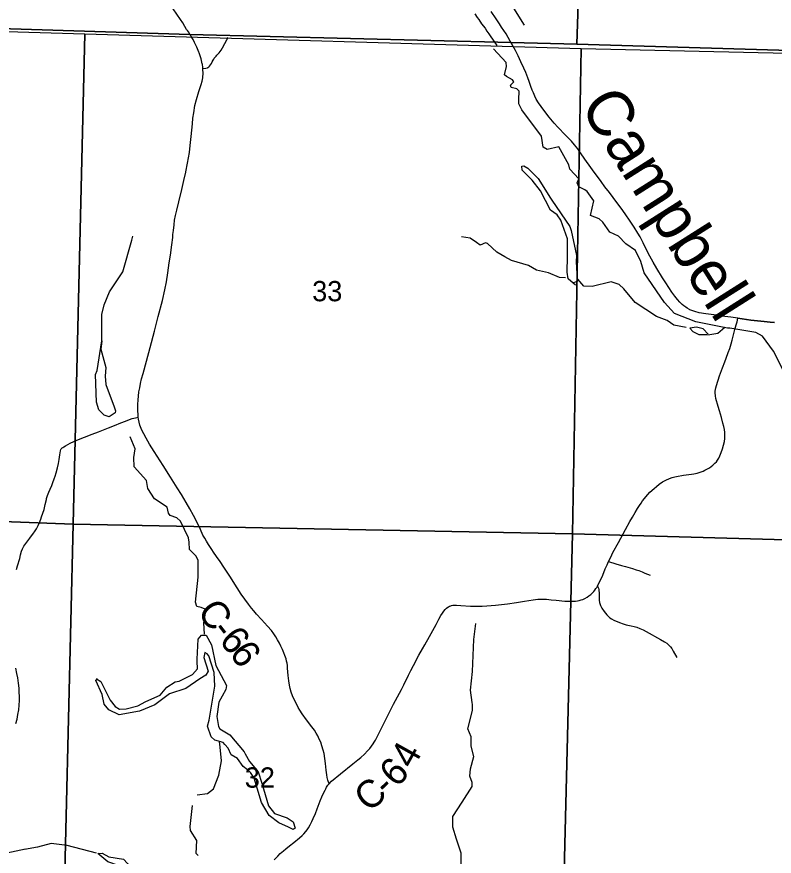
# Model space of a CAD drawing. Extents: x 0 to 34, y 0 to 22.
# Drawn here: x 5.063 to 6.627, y 14.902 to 16.635 of the extents above; entities that cross this region are included whole.
import ezdxf

# ---------------------------------------------------------------- set-up
doc = ezdxf.new("R2010")
doc.units = 0
for name, color, linetype in [('GM_X_Corporation', 7, 'Continuous'), ('GM_X_County', 7, 'Continuous'), ('GM_X_County_Road', 7, 'Continuous'), ('GM_X_County_Road_Text', 7, 'Continuous'), ('GM_X_Minor_River', 7, 'Continuous'), ('GM_X_Minor_River_Text', 7, 'Continuous'), ('GM_X_Rail_Line', 7, 'Continuous'), ('GM_X_Section_Text', 7, 'Continuous'), ('GM_X_State_Route', 7, 'Continuous'), ('GM_X_Township_Road', 7, 'Continuous')]:
    doc.layers.add(name, color=color, linetype=linetype)

msp = doc.modelspace()

# ---------------------------------------------------------------- linework, layer by layer
at = {"layer": 'GM_X_Corporation'}
for points in [[(9.4, 16.4853), (9.4, 20.4), (2.6, 20.4), (2.6, 16.6918), (3.1555, 16.6686), (3.1684, 16.6682), (4.0515, 16.6368), (4.1011, 16.6362), (4.1867, 16.6352), (4.5473, 16.6256), (4.6351, 16.6229), (5.4202, 16.5982), (6.0834, 16.5816), (6.2194, 16.578), (8.0963, 16.5226), (9.09, 16.4927)], [(6.2895, 20.4), (2.6, 20.4), (2.6, 16.6918), (3.1555, 16.6686), (3.1684, 16.6682), (4.0515, 16.6368), (4.1011, 16.6362), (4.1867, 16.6352), (4.5473, 16.6256), (4.6351, 16.6229), (5.4202, 16.5982), (6.0834, 16.5816), (6.2194, 16.578), (6.2729, 18.2077), (6.2744, 18.4654), (6.2786, 18.5898), (6.292, 18.5898), (6.2926, 19.1539), (6.2942, 19.6131), (6.2595, 19.6124)], [(9.4, 16.4853), (9.4, 20.4), (6.2895, 20.4), (6.2595, 19.6124), (6.2942, 19.6131), (6.2926, 19.1539), (6.292, 18.5898), (6.2786, 18.5898), (6.2744, 18.4654), (6.2729, 18.2077), (6.2194, 16.578), (8.0963, 16.5226), (9.09, 16.4927)], [(2.6, 16.6918), (2.6, 13.6), (9.4, 13.6), (9.4, 16.4853), (9.09, 16.4927), (8.0963, 16.5226), (6.2194, 16.578), (6.0834, 16.5816), (5.4202, 16.5982), (4.6351, 16.6229), (4.5473, 16.6256), (4.1867, 16.6352), (4.1011, 16.6362), (4.0515, 16.6368), (3.1684, 16.6682), (3.1555, 16.6686)], [(5.2032, 16.5997), (5.1793, 15.5873), (4.1616, 15.6255), (4.1862, 16.6297)], [(6.2277, 16.5693), (6.2098, 15.5669), (5.1793, 15.5873), (5.2032, 16.5997)], [(7.2336, 16.5466), (7.2151, 15.5388), (6.2098, 15.5669), (6.2277, 16.5693)], [(5.1793, 15.5873), (5.155, 14.5827), (4.1372, 14.6117), (4.1616, 15.6255)], [(5.1793, 15.5873), (6.2098, 15.5669), (6.1855, 14.5629), (5.155, 14.5827)], [(6.2098, 15.5669), (7.2151, 15.5388), (7.1913, 14.5276), (6.1855, 14.5629)]]:
    msp.add_lwpolyline(points, close=True, dxfattribs=at)
msp.add_lwpolyline([(4.5781, 13.6), (9.4, 13.6), (9.4, 16.4853), (9.09, 16.4927), (8.0963, 16.5226), (6.2194, 16.578), (6.0834, 16.5816), (5.4202, 16.5982), (4.6351, 16.6229)], dxfattribs=at)
at = {"layer": 'GM_X_County'}
msp.add_lwpolyline([(9.4, 16.4853), (9.09, 16.4927), (8.0963, 16.5226), (6.2194, 16.578), (6.0834, 16.5816), (5.4202, 16.5982), (4.6351, 16.6229), (4.5473, 16.6256), (4.1867, 16.6352), (4.1011, 16.6362), (4.0515, 16.6368), (3.1684, 16.6682), (3.1555, 16.6686), (2.6, 16.6918)], dxfattribs=at)
at = {"layer": 'GM_X_County_Road'}
for points in [[(5.5941, 14.8939), (5.6013, 14.9018), (5.6067, 14.9072), (5.6132, 14.9131), (5.6178, 14.9171), (5.6255, 14.9231), (5.6345, 14.9303), (5.6464, 14.9393), (5.6518, 14.9442), (5.6556, 14.9482), (5.6593, 14.9526), (5.6621, 14.9563), (5.6648, 14.9601), (5.6685, 14.9663), (5.6721, 14.9732), (5.6749, 14.9798), (5.6792, 14.9899), (5.6828, 14.9994), (5.6893, 15.0157), (5.6928, 15.0241), (5.6962, 15.0317), (5.6991, 15.0378), (5.7008, 15.041), (5.7024, 15.0442), (5.7052, 15.0484), (5.7074, 15.0512), (5.7047, 15.0588), (5.7034, 15.064), (5.7025, 15.0698), (5.7015, 15.0795), (5.7002, 15.0928), (5.699, 15.1032), (5.6973, 15.1135), (5.6955, 15.1205), (5.6927, 15.1297), (5.6902, 15.137), (5.6873, 15.1436), (5.684, 15.1501), (5.6807, 15.1557), (5.6771, 15.1616), (5.672, 15.1689), (5.6609, 15.1834), (5.6518, 15.1957), (5.6471, 15.2029), (5.6439, 15.2087), (5.6385, 15.2187), (5.6342, 15.2277), (5.6318, 15.2331), (5.6293, 15.2402), (5.6271, 15.2476), (5.6255, 15.2545), (5.624, 15.2638), (5.6229, 15.2748), (5.6218, 15.2901), (5.6213, 15.2953), (5.6206, 15.2999), (5.6197, 15.3041), (5.6185, 15.3092), (5.6163, 15.3159), (5.6141, 15.3218), (5.6113, 15.3282), (5.6081, 15.3352), (5.6049, 15.3414), (5.6011, 15.3483), (5.5974, 15.3543), (5.5932, 15.3605), (5.5882, 15.3677), (5.5806, 15.3764), (5.5677, 15.3903), (5.5575, 15.4017), (5.5519, 15.4081), (5.5471, 15.414), (5.5409, 15.4221), (5.5333, 15.4321), (5.5261, 15.4425), (5.5176, 15.4555), (5.5024, 15.4796), (5.4916, 15.496), (5.481, 15.512), (5.4786, 15.5156), (5.4703, 15.5275), (5.4638, 15.5371), (5.4586, 15.5451), (5.4542, 15.5523), (5.4506, 15.5583), (5.447, 15.5644), (5.4416, 15.5759), (5.4364, 15.5875), (5.4276, 15.6048), (5.42, 15.6187), (5.4124, 15.6322), (5.4028, 15.6483), (5.3939, 15.6624), (5.38, 15.6844), (5.3648, 15.7085), (5.3465, 15.7372), (5.3369, 15.7524), (5.3295, 15.7649), (5.3246, 15.7735), (5.3221, 15.7785), (5.3194, 15.7847), (5.3169, 15.7912), (5.3151, 15.7976), (5.3138, 15.8041), (5.3135, 15.8079), (5.313, 15.813), (5.3127, 15.8219), (5.3128, 15.8342), (5.3131, 15.8439), (5.3136, 15.8517), (5.3147, 15.8601), (5.3163, 15.8687), (5.3181, 15.8775), (5.3203, 15.8871), (5.3232, 15.8979), (5.3306, 15.9234), (5.3382, 15.9519), (5.3467, 15.9855), (5.3546, 16.0159), (5.3634, 16.0492), (5.3685, 16.0706), (5.3719, 16.0876), (5.3747, 16.1057), (5.3775, 16.1266), (5.3798, 16.1427), (5.3827, 16.1638), (5.3845, 16.1786), (5.3851, 16.1851), (5.386, 16.1936), (5.3872, 16.2049), (5.3885, 16.2146), (5.3903, 16.2244), (5.3927, 16.2354), (5.3969, 16.2525), (5.4031, 16.2777), (5.4076, 16.2966), (5.4115, 16.314), (5.4117, 16.3147), (5.4152, 16.3325), (5.4191, 16.3542), (5.4209, 16.3687), (5.4227, 16.3876), (5.4251, 16.4136), (5.4263, 16.4256), (5.4279, 16.4365), (5.4304, 16.4514), (5.4336, 16.4637), (5.4387, 16.4802), (5.4433, 16.4948), (5.4454, 16.5017), (5.4467, 16.5084), (5.447, 16.5116), (5.4474, 16.516), (5.447, 16.5281), (5.4469, 16.5297), (5.4457, 16.5368), (5.4456, 16.5374), (5.4431, 16.5481), (5.4392, 16.5601), (5.4386, 16.5617), (5.4343, 16.5719), (5.4296, 16.5816), (5.4265, 16.5875), (5.4226, 16.594), (5.4168, 16.6033)], [(5.7074, 15.0512), (5.7127, 15.0564), (5.731, 15.0719), (5.7566, 15.0921), (5.7671, 15.1006), (5.7731, 15.1054), (5.7805, 15.1123), (5.787, 15.1191), (5.7913, 15.1239), (5.7953, 15.1291), (5.7984, 15.1334), (5.8006, 15.137), (5.8031, 15.141), (5.8084, 15.1509), (5.8214, 15.1769), (5.833, 15.2004), (5.8407, 15.2154), (5.8567, 15.2458), (5.8616, 15.2552), (5.8717, 15.2756), (5.8762, 15.2848), (5.8817, 15.2952), (5.893, 15.3164), (5.9002, 15.3295), (5.9049, 15.3381), (5.9148, 15.3552), (5.9219, 15.3678), (5.9284, 15.38), (5.9342, 15.391), (5.9384, 15.3986), (5.9415, 15.4034), (5.9445, 15.4075), (5.9471, 15.411), (5.95, 15.4139), (5.9524, 15.4158), (5.9539, 15.4168), (5.9559, 15.4178), (5.9586, 15.4188), (5.9602, 15.4193), (5.9632, 15.4198), (5.9658, 15.42), (5.9706, 15.4198), (5.9798, 15.4195), (5.9994, 15.4182), (6.0144, 15.4179), (6.0233, 15.4182), (6.0333, 15.4185), (6.0425, 15.4191), (6.0514, 15.42), (6.0761, 15.4229), (6.0944, 15.4257), (6.1113, 15.4283), (6.1289, 15.431), (6.1388, 15.4322), (6.1471, 15.4324), (6.1561, 15.4322), (6.1664, 15.431), (6.1762, 15.43), (6.1944, 15.4282), (6.204, 15.4279), (6.211, 15.4281), (6.216, 15.4284), (6.2202, 15.4289), (6.2237, 15.4296), (6.2277, 15.4307), (6.2313, 15.4318), (6.2353, 15.4335), (6.2401, 15.4363), (6.2441, 15.439), (6.248, 15.4422), (6.2513, 15.4452), (6.2541, 15.4483), (6.2562, 15.451), (6.2584, 15.4541), (6.2601, 15.4565), (6.2619, 15.4595), (6.2648, 15.4651), (6.2686, 15.4732), (6.2727, 15.4819), (6.2779, 15.495), (6.2815, 15.5035), (6.2848, 15.5102), (6.289, 15.519), (6.2935, 15.5285), (6.3054, 15.5496), (6.3195, 15.576), (6.3286, 15.5927), (6.3338, 15.6017), (6.3395, 15.6114), (6.3444, 15.6194), (6.3483, 15.6254), (6.3516, 15.6303), (6.3549, 15.6352), (6.3588, 15.64), (6.3619, 15.6438), (6.37, 15.6532), (6.3785, 15.661), (6.3834, 15.6652), (6.3889, 15.6696), (6.3963, 15.6742), (6.4027, 15.6777), (6.4107, 15.6812), (6.4162, 15.6832), (6.4213, 15.6847), (6.4251, 15.6856), (6.439, 15.688), (6.4556, 15.6902), (6.4609, 15.6911), (6.4676, 15.6927), (6.4718, 15.694), (6.4761, 15.6954), (6.4798, 15.6968), (6.4833, 15.6985), (6.4889, 15.7012), (6.493, 15.7037), (6.4965, 15.7063), (6.4999, 15.709), (6.504, 15.7129), (6.5072, 15.7161), (6.5095, 15.719), (6.5122, 15.7236), (6.5144, 15.7281), (6.5174, 15.7348), (6.52, 15.7427), (6.5219, 15.7502), (6.5238, 15.7577), (6.5248, 15.7639), (6.525, 15.7709), (6.5247, 15.7763), (6.5237, 15.7825), (6.5224, 15.7886), (6.5208, 15.7958), (6.5176, 15.8074), (6.5134, 15.8213), (6.511, 15.8301), (6.5064, 15.8467), (6.5054, 15.8518), (6.5048, 15.8581), (6.505, 15.8617), (6.5063, 15.8683), (6.5074, 15.8732), (6.514, 15.8937), (6.5197, 15.9097), (6.5248, 15.9224), (6.5276, 15.93), (6.5319, 15.9418), (6.5347, 15.95), (6.5375, 15.9594), (6.5396, 15.9673), (6.5438, 15.9834), (6.5453, 15.989), (6.5468, 15.9941), (6.5482, 15.9986), (6.5488, 16.0006), (6.5501, 16.0051), (6.5517, 16.0123)], [(6.5517, 16.0123), (6.5782, 16.0086), (6.6056, 16.0054), (6.618, 16.0044), (6.6273, 16.0037)]]:
    msp.add_lwpolyline(points, dxfattribs=at)
at = {"layer": 'GM_X_Minor_River'}
for points in [[(6.0081, 16.6406), (6.0133, 16.6332), (6.0169, 16.6291), (6.0225, 16.6202), (6.0297, 16.6114), (6.033, 16.6047), (6.0373, 16.5995), (6.0398, 16.595), (6.0537, 16.5756)], [(6.6461, 15.9039), (6.625, 15.944), (6.6027, 15.9754), (6.5884, 15.983), (6.5351, 15.9921), (6.5305, 15.992), (6.465, 16.0049), (6.4205, 16.0218), (6.4003, 16.0448), (6.3579, 16.106), (6.3513, 16.1297), (6.3401, 16.1519), (6.3204, 16.1658), (6.3049, 16.1814), (6.2869, 16.1901), (6.2731, 16.2103), (6.265, 16.2173), (6.2474, 16.2241), (6.2543, 16.2549), (6.2402, 16.2736), (6.2359, 16.2773), (6.2232, 16.2838), (6.2196, 16.2917), (6.2229, 16.3001), (6.2046, 16.3198), (6.2025, 16.3288), (6.1819, 16.3659), (6.1581, 16.3604), (6.1496, 16.3652), (6.1464, 16.3878), (6.1057, 16.4422), (6.099, 16.4546), (6.0992, 16.4637), (6.0999, 16.4811), (6.0952, 16.4856), (6.0834, 16.4887), (6.0822, 16.4932), (6.0888, 16.5002), (6.0861, 16.5047), (6.0738, 16.5112), (6.0699, 16.5149), (6.0741, 16.5317), (6.0731, 16.5404), (6.0467, 16.5684)], [(6.2165, 16.0805), (6.2014, 16.0938), (6.1988, 16.1071), (6.2, 16.1397), (6.1995, 16.176), (6.1861, 16.2144), (6.1782, 16.226), (6.1647, 16.2355), (6.1437, 16.2756), (6.1269, 16.2976), (6.1059, 16.3176), (6.1057, 16.3263), (6.1095, 16.3271), (6.118, 16.3224), (6.1389, 16.3009), (6.1649, 16.2598), (6.1677, 16.2557), (6.2046, 16.2019), (6.2075, 16.1936), (6.2185, 16.142), (6.2177, 16.1291), (6.2197, 16.0912), (6.2179, 16.0874), (6.2103, 16.0846)], [(5.2379, 15.9659), (5.2382, 16.0198), (5.2427, 16.0396), (5.2542, 16.0671), (5.2813, 16.1079), (5.3003, 16.1731), (5.3024, 16.1815)], [(6.196, 16.096), (6.1835, 16.0965), (6.1609, 16.1058), (6.1357, 16.1117), (6.1192, 16.1208), (6.0844, 16.1314), (6.0705, 16.1387), (6.054, 16.1489), (6.0346, 16.1667), (6.0304, 16.1681), (6.0191, 16.163), (6.0118, 16.1689), (5.9987, 16.1777), (5.9808, 16.1803)], [(6.4451, 15.9931), (6.4196, 15.9982), (6.4057, 16.0074), (6.3835, 16.016), (6.3392, 16.045), (6.3161, 16.0733), (6.3068, 16.0822), (6.29, 16.0871), (6.2507, 16.0779), (6.2333, 16.0783), (6.2211, 16.0931)], [(6.4906, 15.9793), (6.4797, 15.9901), (6.466, 15.994), (6.4524, 15.9918), (6.4586, 15.9847), (6.4713, 15.9785), (6.4883, 15.9785)], [(6.5247, 15.9931), (6.5103, 15.9809), (6.4895, 15.9774)], [(5.2379, 15.9659), (5.2364, 15.9484), (5.2464, 15.9104), (5.2449, 15.8925), (5.2464, 15.8755), (5.2634, 15.8292), (5.2663, 15.821), (5.266, 15.8172), (5.2533, 15.8089), (5.2429, 15.8121), (5.2317, 15.8229), (5.2271, 15.8391), (5.2251, 15.8959), (5.2283, 15.9047), (5.2379, 15.9659)], [(5.4503, 15.3602), (5.449, 15.3837), (5.453, 15.4077), (5.4518, 15.4115), (5.4433, 15.4151), (5.4342, 15.4175), (5.4317, 15.4258), (5.437, 15.4779), (5.4373, 15.512), (5.4333, 15.5214), (5.4193, 15.5351), (5.4182, 15.5499), (5.4173, 15.5586), (5.4009, 15.5931), (5.3928, 15.6001), (5.379, 15.6051), (5.3759, 15.6096), (5.3733, 15.6224), (5.3471, 15.6393), (5.3333, 15.6606), (5.3303, 15.6772), (5.3046, 15.7058), (5.3041, 15.7248), (5.3072, 15.7426), (5.2967, 15.7671)], [(5.98, 14.8719), (5.9799, 14.908), (5.9705, 14.9369), (5.9627, 14.9614), (5.963, 14.9834), (5.9824, 15.013), (6.0026, 15.0457), (6.0031, 15.0537), (5.9983, 15.0669), (5.9995, 15.0821), (6.0065, 15.1072), (6.0007, 15.1287), (6.0006, 15.1484), (5.9942, 15.1646), (6.0039, 15.2023), (6.0036, 15.2149), (6.0032, 15.219), (5.9992, 15.2447), (6.0036, 15.2831), (6.0063, 15.3488), (6.0104, 15.3822)], [(5.2269, 15.2677), (5.2361, 15.2626), (5.2553, 15.2236), (5.2654, 15.2105), (5.2747, 15.2054), (5.2883, 15.2057), (5.3125, 15.2123), (5.3293, 15.2211), (5.3586, 15.2342), (5.3723, 15.2508), (5.3895, 15.2615), (5.3979, 15.2628), (5.4252, 15.2767), (5.436, 15.2883), (5.4349, 15.3045), (5.4348, 15.3083), (5.4372, 15.3497), (5.4439, 15.3582), (5.4534, 15.3577), (5.4648, 15.3378), (5.4734, 15.2956), (5.4956, 15.2543), (5.4943, 15.2456), (5.487, 15.2322), (5.4801, 15.2195), (5.4754, 15.1902), (5.4793, 15.1694), (5.4817, 15.1645), (5.5025, 15.1521), (5.5318, 15.1175), (5.5341, 15.113), (5.5432, 15.0969), (5.5608, 15.0761), (5.5689, 15.0524), (5.5821, 15.0056), (5.595, 14.9896), (5.6207, 14.9807), (5.633, 14.9726), (5.6371, 14.9598), (5.633, 14.9571), (5.6234, 14.9618), (5.6038, 14.9705), (5.5834, 14.9856), (5.5679, 15.0125), (5.5528, 15.0626), (5.5449, 15.0746), (5.5391, 15.0798), (5.5302, 15.0868), (5.518, 15.1036), (5.505, 15.1108), (5.4989, 15.1247), (5.4923, 15.1322), (5.4888, 15.1363), (5.4712, 15.1412), (5.4639, 15.1482), (5.4565, 15.17), (5.4597, 15.1826), (5.4713, 15.2527), (5.4703, 15.2811), (5.4589, 15.3153), (5.4558, 15.3198), (5.4511, 15.3224), (5.4491, 15.3121), (5.4577, 15.2838), (5.4526, 15.2754), (5.4402, 15.2679), (5.4115, 15.2479), (5.3779, 15.2369), (5.3473, 15.2143), (5.3161, 15.201), (5.2738, 15.1933), (5.2523, 15.2042), (5.2429, 15.2153), (5.2391, 15.2353), (5.2259, 15.2646), (5.2292, 15.2685)], [(5.4347, 15.0281), (5.4563, 15.0313), (5.4686, 15.0406), (5.4797, 15.069), (5.4855, 15.0987), (5.482, 15.1335), (5.4812, 15.1372)], [(5.4368, 14.9031), (5.4333, 14.9075), (5.4346, 14.9341), (5.4212, 14.9547), (5.4207, 14.963), (5.4254, 15.0063)], [(5.2272, 14.9079), (5.1669, 14.9236), (5.1337, 14.9278), (5.105, 14.9207), (5.0784, 14.9155)], [(5.0805, 14.9159), (5.0321, 14.9058)], [(5.2314, 14.9072), (5.239, 14.9077), (5.2524, 14.9005), (5.2829, 14.8958), (5.2914, 14.8865), (5.2999, 14.8807), (5.3171, 14.8784), (5.3566, 14.858), (5.3693, 14.8526), (5.377, 14.8464), (5.3779, 14.8418), (5.3614, 14.8308), (5.3397, 14.8361), (5.3107, 14.8597), (5.2862, 14.8682), (5.2761, 14.8786), (5.2726, 14.8827), (5.2507, 14.8902), (5.2302, 14.9072)]]:
    msp.add_lwpolyline(points, dxfattribs=at)
at = {"layer": 'GM_X_Rail_Line'}
msp.add_lwpolyline([(6.0626, 16.6938), (6.1104, 16.6174)], dxfattribs=at)
at = {"layer": 'GM_X_State_Route'}
for points in [[(6.0816, 16.5843), (6.0728, 16.5992), (6.0637, 16.6133), (6.0592, 16.6202), (6.0522, 16.6306), (6.0422, 16.6458)], [(6.5517, 16.0123), (6.5374, 16.0142), (6.5182, 16.0168), (6.5021, 16.0192), (6.4853, 16.0215), (6.4714, 16.0237), (6.4628, 16.0259), (6.4563, 16.0281), (6.4527, 16.0297), (6.4516, 16.0303), (6.447, 16.0328), (6.444, 16.0348), (6.4402, 16.0376), (6.4368, 16.0404), (6.4318, 16.0453), (6.4267, 16.0512), (6.4213, 16.058), (6.4154, 16.0662), (6.4028, 16.0851), (6.3961, 16.0956), (6.3844, 16.1149), (6.3765, 16.128), (6.37, 16.1401), (6.3622, 16.1551), (6.3558, 16.1681), (6.3498, 16.18), (6.3451, 16.1882), (6.3376, 16.2003), (6.3348, 16.2046), (6.3293, 16.2128), (6.3187, 16.2279), (6.3104, 16.2398), (6.3019, 16.2513), (6.2864, 16.2718), (6.2772, 16.2837), (6.269, 16.2948), (6.2616, 16.3047), (6.2547, 16.3141), (6.2478, 16.3235), (6.2358, 16.3407), (6.2268, 16.3534), (6.221, 16.3617), (6.2144, 16.3699), (6.2078, 16.3776), (6.1955, 16.3905), (6.1796, 16.4067), (6.172, 16.4152), (6.162, 16.4273), (6.1531, 16.4387), (6.1451, 16.4495), (6.1401, 16.4567), (6.135, 16.4648), (6.1322, 16.4708), (6.1294, 16.4777), (6.1271, 16.4832), (6.1241, 16.4909), (6.1206, 16.5011), (6.1179, 16.5083), (6.1137, 16.5193), (6.1096, 16.5288), (6.1034, 16.5417), (6.0977, 16.5539), (6.0921, 16.5652), (6.0816, 16.5843)], [(6.6273, 16.0037), (6.618, 16.0044), (6.6056, 16.0054), (6.5782, 16.0086), (6.5517, 16.0123)]]:
    msp.add_lwpolyline(points, dxfattribs=at)
at = {"layer": 'GM_X_Township_Road'}
for points in [[(5.4168, 16.6033), (5.415, 16.6061), (5.4133, 16.6086), (5.4097, 16.6144), (5.4051, 16.6218), (5.4007, 16.6287), (5.3781, 16.6617)], [(5.447, 16.5281), (5.4526, 16.5286), (5.4562, 16.5294), (5.4574, 16.53), (5.4588, 16.531), (5.4607, 16.5326), (5.4627, 16.5355), (5.4644, 16.5382), (5.4663, 16.5416), (5.4683, 16.5453), (5.4692, 16.5469), (5.4704, 16.5489), (5.4721, 16.5511), (5.4741, 16.5534), (5.4757, 16.5552), (5.4786, 16.5584), (5.4804, 16.5604), (5.4824, 16.563), (5.4843, 16.5657), (5.4874, 16.5708), (5.4968, 16.5882), (5.4988, 16.592)], [(5.0703, 15.5239), (5.0725, 15.5313), (5.0743, 15.5362), (5.0756, 15.539), (5.077, 15.5415), (5.0789, 15.5444), (5.0834, 15.5503), (5.0897, 15.558), (5.0972, 15.5683), (5.0994, 15.5715), (5.1032, 15.5778), (5.1066, 15.5842), (5.1095, 15.5909), (5.1121, 15.5977), (5.1139, 15.6024), (5.1165, 15.6099), (5.1189, 15.6175), (5.121, 15.6275), (5.1236, 15.6382), (5.1242, 15.6404), (5.1262, 15.6466), (5.1285, 15.6532), (5.1313, 15.6596), (5.1346, 15.6668), (5.1371, 15.6729), (5.1399, 15.6808), (5.1419, 15.6863), (5.1438, 15.6928), (5.1466, 15.7036), (5.1487, 15.7124), (5.15, 15.7209), (5.1513, 15.73), (5.1527, 15.7385), (5.1534, 15.7411), (5.1541, 15.7424), (5.1554, 15.744), (5.1563, 15.7449), (5.1574, 15.7457), (5.1594, 15.747), (5.1631, 15.749), (5.1731, 15.7544), (5.18, 15.7578), (5.185, 15.7601), (5.1931, 15.7631), (5.2025, 15.7667), (5.2184, 15.7728), (5.2313, 15.7778), (5.245, 15.7833), (5.252, 15.7861), (5.2646, 15.791), (5.2774, 15.7962), (5.2873, 15.8), (5.2952, 15.8032), (5.3006, 15.8051), (5.3042, 15.8061), (5.3079, 15.807), (5.3135, 15.8079)], [(5.0616, 15.4939), (5.0639, 15.5012), (5.0685, 15.5166), (5.0703, 15.5239)], [(6.2848, 15.5102), (6.2999, 15.5055), (6.3112, 15.5021), (6.3198, 15.4995), (6.334, 15.4953), (6.3416, 15.4931), (6.3471, 15.4912), (6.3542, 15.4885), (6.3598, 15.4863), (6.3706, 15.4816)], [(6.2619, 15.4595), (6.2637, 15.4551), (6.2643, 15.4524), (6.2647, 15.4497), (6.265, 15.4462), (6.265, 15.435), (6.2653, 15.4304), (6.266, 15.4255), (6.2678, 15.4191), (6.2704, 15.414), (6.2755, 15.4067), (6.2809, 15.3999), (6.2849, 15.3956), (6.2873, 15.3935), (6.2905, 15.3914), (6.2958, 15.3887), (6.3073, 15.3841), (6.3148, 15.3814), (6.321, 15.3796), (6.331, 15.3772), (6.3375, 15.3757), (6.3431, 15.3742), (6.3495, 15.3719), (6.3558, 15.3691), (6.3625, 15.3653), (6.3921, 15.3489), (6.3999, 15.3444), (6.4046, 15.3415), (6.4085, 15.3382), (6.4122, 15.3342), (6.415, 15.3304), (6.4181, 15.3249), (6.4254, 15.3116)], [(5.0607, 15.1754), (5.0633, 15.1847), (5.065, 15.1942), (5.0666, 15.2038), (5.0677, 15.2134), (5.0682, 15.223), (5.0675, 15.2488), (5.0664, 15.2591), (5.0648, 15.2697), (5.0628, 15.2792), (5.0609, 15.2897)]]:
    msp.add_lwpolyline(points, dxfattribs=at)

# ---------------------------------------------------------------- texts
at = {"layer": 'GM_X_County_Road_Text'}
for s, rotation, p in [('C', 304.9113, (5.4336, 15.4072)), ('-', 307.6792, (5.4618, 15.3668)), ('6', 310.8745, (5.4782, 15.3458)), ('6', 305.3299, (5.5, 15.3207)), ('4', 60.8432, (5.8803, 15.0795)), ('6', 46.5955, (5.8472, 15.0417)), ('C', 39.86, (5.7891, 14.9908)), ('-', 43.2235, (5.8276, 15.0231))]:
    msp.add_text(s, height=0.0568, rotation=rotation, dxfattribs=at).set_placement(p)
at = {"layer": 'GM_X_Minor_River_Text'}
msp.add_text('Campbell', height=0.09463, rotation=302.3315, dxfattribs=at).set_placement((6.2235, 16.4504))
at = {"layer": 'GM_X_Section_Text'}
for s, p in [('33', (5.6725, 16.0473)), ('32', (5.5333, 15.0432))]:
    msp.add_text(s, height=0.04186, rotation=0, dxfattribs=at).set_placement(p)

doc.saveas('drawing.dxf')
